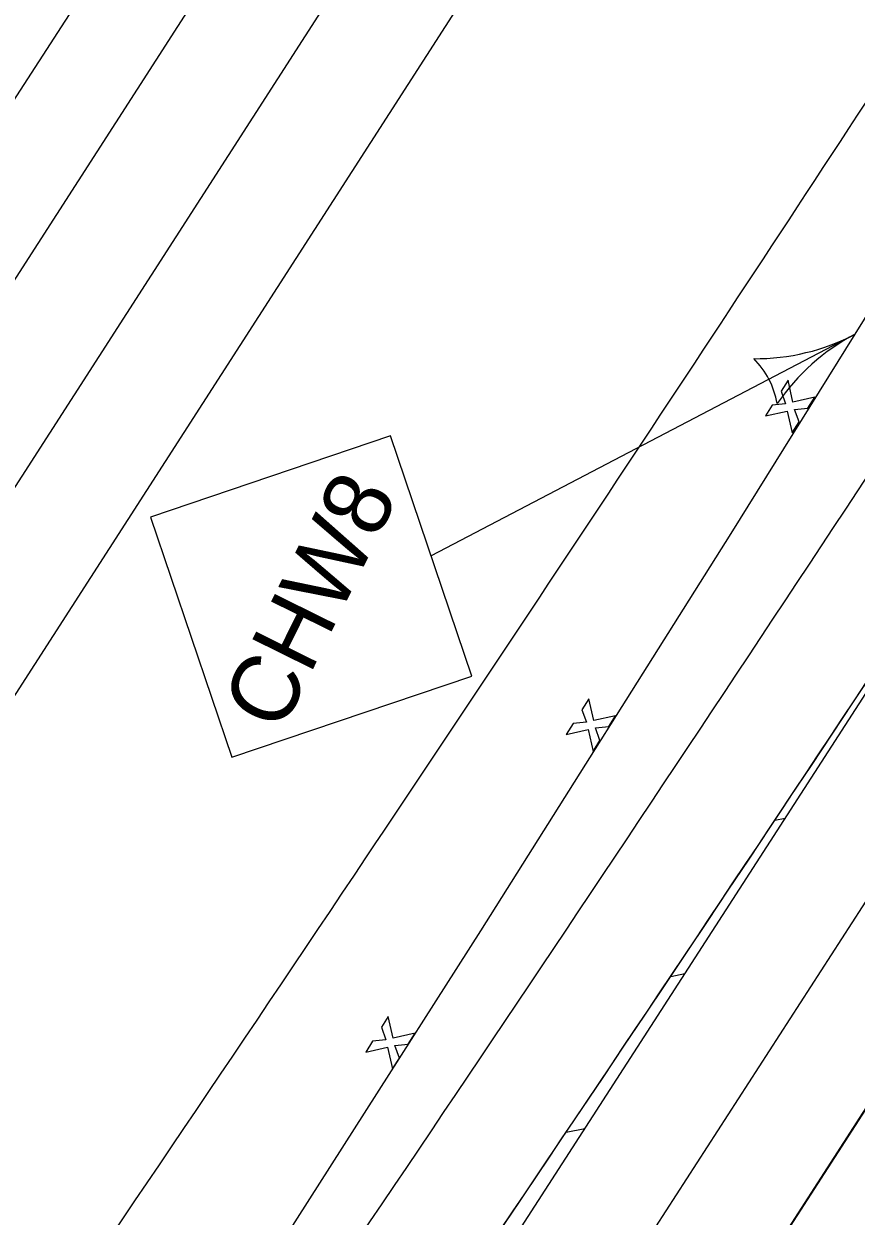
# Model space of a CAD drawing. Extents: x 14097936 to 14128734, y 8632000 to 8683104.
# Drawn here: x 14119353.7 to 14119442.3, y 8669266 to 8669393 of the extents above; entities that cross this region are included whole.
import ezdxf

# ---------------------------------------------------------------- set-up
doc = ezdxf.new("R2010")
doc.units = 0
for name, color, linetype in [('Cell', 7, 'Continuous'), ('dsnPaintExistingChannelizingLaneWhite', 7, 'Continuous'), ('dsnPaintExistingDoubleCenterYellow', 7, 'Continuous'), ('dsnPaintPlaceBrokenLaneWhite', 7, 'Continuous'), ('dsnPaintPlaceChannelizingLaneYellow', 7, 'Continuous'), ('dsnPaintPlaceEdgeLineRightWhite', 7, 'Continuous'), ('dsnPavementRmvl', 7, 'Continuous'), ('dsnShadingPaved', 7, 'Continuous'), ('dsnStdLabel', 7, 'Continuous'), ('dsnStgShadingPropPav', 7, 'Continuous'), ('dsnTapePlaceChannelizingLaneWhite', 7, 'Continuous')]:
    doc.layers.add(name, color=color, linetype=linetype)

msp = doc.modelspace()

# ---------------------------------------------------------------- linework, layer by layer
at = {"layer": 'Cell'}
for p, q in [((14119435.08, 8669355.01), (14119434.35, 8669353.85)), ((14119434.35, 8669353.85), (14119434.83, 8669352.51)), ((14119435.6, 8669352.68), (14119435.08, 8669355.01)), ((14119437.93, 8669353.21), (14119435.6, 8669352.68)), ((14119437.2, 8669352.04), (14119437.93, 8669353.21)), ((14119433.41, 8669352.37), (14119432.68, 8669351.21)), ((14119432.68, 8669351.21), (14119435, 8669351.73)), ((14119434.83, 8669352.51), (14119433.41, 8669352.37)), ((14119435, 8669351.73), (14119435.53, 8669349.4)), ((14119435.78, 8669351.91), (14119437.2, 8669352.04)), ((14119436.26, 8669350.57), (14119435.78, 8669351.91)), ((14119435.53, 8669349.4), (14119436.26, 8669350.57)), ((14119413.86, 8669321.08), (14119413.13, 8669319.91)), ((14119414.38, 8669318.75), (14119413.86, 8669321.08)), ((14119413.13, 8669319.91), (14119413.61, 8669318.57)), ((14119412.19, 8669318.43), (14119411.45, 8669317.27)), ((14119413.61, 8669318.57), (14119412.19, 8669318.43)), ((14119416.71, 8669319.27), (14119414.38, 8669318.75)), ((14119415.98, 8669318.11), (14119416.71, 8669319.27)), ((14119411.45, 8669317.27), (14119413.78, 8669317.8)), ((14119413.78, 8669317.8), (14119414.31, 8669315.47)), ((14119414.56, 8669317.97), (14119415.98, 8669318.11)), ((14119415.04, 8669316.63), (14119414.56, 8669317.97)), ((14119414.31, 8669315.47), (14119415.04, 8669316.63)), ((14119392.5, 8669287.24), (14119391.76, 8669286.08)), ((14119393.02, 8669284.91), (14119392.5, 8669287.24)), ((14119391.76, 8669286.08), (14119392.25, 8669284.73)), ((14119395.35, 8669285.43), (14119393.02, 8669284.91)), ((14119394.61, 8669284.27), (14119395.35, 8669285.43)), ((14119390.83, 8669284.6), (14119390.09, 8669283.43)), ((14119390.09, 8669283.43), (14119392.42, 8669283.96)), ((14119392.25, 8669284.73), (14119390.83, 8669284.6)), ((14119392.42, 8669283.96), (14119392.94, 8669281.63)), ((14119393.2, 8669284.13), (14119394.61, 8669284.27)), ((14119393.68, 8669282.79), (14119393.2, 8669284.13)), ((14119392.94, 8669281.63), (14119393.68, 8669282.79))]:
    msp.add_line(p, q, dxfattribs=at)
at = {"layer": 'dsnPaintExistingChannelizingLaneWhite'}
for p, q in [((14119434.72, 8669493.24), (14119231.48, 8669177.36)), ((14119251.66, 8669164.37), (14119454.9, 8669480.25))]:
    msp.add_line(p, q, dxfattribs=at)
at = {"layer": 'dsnPaintExistingDoubleCenterYellow'}
msp.add_line((14119241.57, 8669170.86), (14119444.81, 8669486.75), dxfattribs=at)
at = {"layer": 'dsnPaintPlaceBrokenLaneWhite'}
msp.add_line((14119527.44, 8669429.79), (14119185.09, 8668899.43), dxfattribs=at)
at = {"layer": 'dsnPaintPlaceChannelizingLaneYellow'}
for p, q in [((14119397.41, 8669250.48), (14119477.17, 8669374.04)), ((14119433.69, 8669308.14), (14119434.77, 8669308.36)), ((14119422.59, 8669291.5), (14119424.08, 8669291.8)), ((14119411.46, 8669274.89), (14119413.42, 8669275.28))]:
    msp.add_line(p, q, dxfattribs=at)
msp.add_arc((14111644.26, 8674494.18), 9357.9, 325.262476, 326.828528, dxfattribs=at)
at = {"layer": 'dsnPaintPlaceEdgeLineRightWhite'}
msp.add_line((14119195.17, 8668892.92), (14119537.53, 8669423.29), dxfattribs=at)
at = {"layer": 'dsnPavementRmvl'}
for p, q in [((14119434.72, 8669493.24), (14119231.48, 8669177.36)), ((14119251.66, 8669164.37), (14119454.9, 8669480.25))]:
    msp.add_line(p, q, dxfattribs=at)
at = {"layer": 'dsnShadingPaved'}
msp.add_line((14119175.01, 8668905.94), (14119517.35, 8669436.29), dxfattribs=at)
for points in [[(14119238.52, 8669044.85), (14119265.99, 8669086.65), (14119293.47, 8669128.44), (14119320.94, 8669170.24), (14119348.3, 8669212.11), (14119375.45, 8669254.16), (14119402.36, 8669296.35), (14119429.03, 8669338.69), (14119455.46, 8669381.17), (14119481.65, 8669423.79), (14119497.35, 8669449.49)], [(14119537.53, 8669423.29), (14119537.53, 8669423.29), (14119195.17, 8668892.92)]]:
    msp.add_lwpolyline(points, dxfattribs=at)
for radius in [9000, 9000, 9012]:
    msp.add_arc((14111929.66, 8674298.73), radius, 325.249705, 327.157368, dxfattribs=at)
at = {"layer": 'dsnStdLabel'}
for p, q in [((14119425.08, 8669496.82), (14119303.44, 8669308.96)), ((14119442.24, 8669359.93), (14119397.08, 8669336.29))]:
    msp.add_line(p, q, dxfattribs=at)
msp.add_lwpolyline([(14119375.83, 8669314.85), (14119401.4, 8669323.5), (14119392.75, 8669349.08), (14119367.17, 8669340.42)], close=True, dxfattribs=at)
for centre, radius, start, end in [((14119431.6, 8669380.26), 22.95, 269.5585, 297.6298), ((14119452.89, 8669339.6), 22.95, 117.6296, 145.7009), ((14119425.2, 8669351.01), 8.86, 9.8955, 45.3639)]:
    msp.add_arc(centre, radius, start, end, dxfattribs=at)
at = {"layer": 'dsnStgShadingPropPav'}
for p, q in [((14119434.72, 8669493.24), (14119231.48, 8669177.36)), ((14119251.66, 8669164.37), (14119454.9, 8669480.25))]:
    msp.add_line(p, q, dxfattribs=at)
for start, end in [(326.199346, 326.878345), (325.249705, 326.199346)]:
    msp.add_arc((14111929.66, 8674298.73), 8978, start, end, dxfattribs=at)
at = {"layer": 'dsnTapePlaceChannelizingLaneWhite'}
msp.add_lwpolyline([(14119238.52, 8669044.85), (14119265.99, 8669086.65), (14119293.47, 8669128.44), (14119320.94, 8669170.24), (14119348.3, 8669212.11), (14119375.45, 8669254.16), (14119402.36, 8669296.35), (14119429.03, 8669338.69), (14119455.46, 8669381.17), (14119481.65, 8669423.79), (14119497.35, 8669449.49)], dxfattribs=at)

# ---------------------------------------------------------------- texts
at = {"layer": 'dsnStdLabel'}
msp.add_text('CHW8', height=7.2, rotation=63.6912, dxfattribs=at).set_placement((14119381.05, 8669317.29))

doc.saveas('drawing.dxf')
